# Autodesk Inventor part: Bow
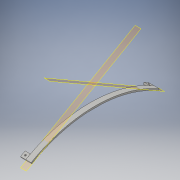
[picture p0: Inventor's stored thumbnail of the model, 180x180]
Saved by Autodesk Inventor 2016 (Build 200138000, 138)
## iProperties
Created: 2016-03
Part Number: Bow
Material: Generic
Document SubType Name: Modeling
Designer: fisher
Density: 1 g/cm^3
Appearance: Default
Author: fisher
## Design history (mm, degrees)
sketch "Sketch1"
  geometry: L1 (0, -152.209)-(3.301, -154.112); L2 (0, 152.209)-(3.301, 154.112); A1 r 304.8 centre (-264.074, 0) between (0, -152.209) and (0, 152.209); A2 r 308.61 centre (-264.074, 0) between (3.301, -154.112) and (3.301, 154.112); 2 further points
  constraints: 4 end point, 4 point on circle, 2 centre point, 2 coincident
  dimensions: "d0" = 304.419 distance of L2.start L1.start; "d2" = 304.8 radius of A1; "d3" = 308.61 radius of A2
extrude "Extrusion1" new body sketch "Sketch1" distance "d4" = 12.7; taper "d5" = 0 deg
workplane "Work Plane1"
workplane "Work Plane2"
sketch "Sketch5"
  geometry: L1 (0, 0)-(12.7, 0); L2 (12.7, 0)-(12.7, -12.7); L3 (12.7, -12.7)-(0, -12.7); L4 (0, -12.7)-(0, 0); C1 r 1.905 at (6.35, -6.35); 2 further points
  constraints: 8 end point, 2 parallel, 1 centre point, 1 coincident, 1 horizontal, 1 perpendicular
  dimensions: "d27" = 12.7 distance of L1.end L2.end; "d28" = 12.7 distance of L2.end L3.end; "d29" = 3.81 diameter of C1
extrude "Extrusion5" join sketch "Sketch5" distance "d30" = 3.81; taper "d31" = 0 deg
sketch "Sketch6"
  geometry: L1 (-12.7, 0)-(0, 0); L2 (0, 0)-(0, -12.7); L3 (0, -12.7)-(-12.7, -12.7); L4 (-12.7, -12.7)-(-12.7, 0); C1 r 1.905 at (-6.35, -6.35); 2 further points
  constraints: 8 end point, 2 parallel, 1 centre point, 1 coincident, 1 horizontal, 1 perpendicular
  dimensions: "d32" = 12.7 distance of L3.end L1.start; "d33" = 12.7 distance of L2.end L3.end; "d34" = 3.81 diameter of C1
extrude "Extrusion6" join sketch "Sketch6" distance "d35" = 3.81; taper "d36" = 0 deg
sketch "Sketch7"
  geometry: L1 (19.05, 40.13)-(-19.05, 40.13); L2 (-19.05, 40.13)-(-19.05, 43.947); L3 (-19.05, 43.947)-(19.05, 43.947); L4 (19.05, 43.947)-(19.05, 40.13); A1 r 308.61 centre (0, -264.074) between (154.112, 3.301) and (-154.112, 3.301) reference; A2 r 304.8 centre (0, -264.074) between (152.209, 0) and (-152.209, 0) reference; 1 further point
  constraints: 8 end point, 2 parallel, 2 point on circle, 1 horizontal, 1 perpendicular
  dimensions: "d37" = 38.1 distance of L1.start L1.end; "d38" = 19.05 distance from line of point (0, 0) L4
extrude "Extrusion7" join sketch "Sketch7" stored distance "d39" = 3.81; taper "d40" = 0 deg
body "Solid1"
other parameters: "d6" = 90 deg
